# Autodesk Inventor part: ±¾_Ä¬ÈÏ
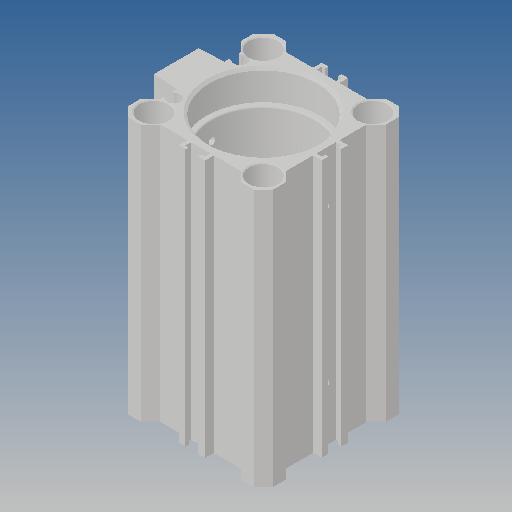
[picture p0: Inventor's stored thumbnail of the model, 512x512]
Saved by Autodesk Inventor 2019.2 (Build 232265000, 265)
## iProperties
Created: 2011-12
Part Number: ±¾_Ä¬ÈÏ
Material: Ogólny
Document SubType Name: Modeling
Designer: CADENGINEERING4
Density: 1 g/cm^3
Appearance: Domyślna
Author: CADENGINEERING4
Revision Number: ÈÎºÎ
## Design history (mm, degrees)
feature "NONE"
node "Bryła1"
